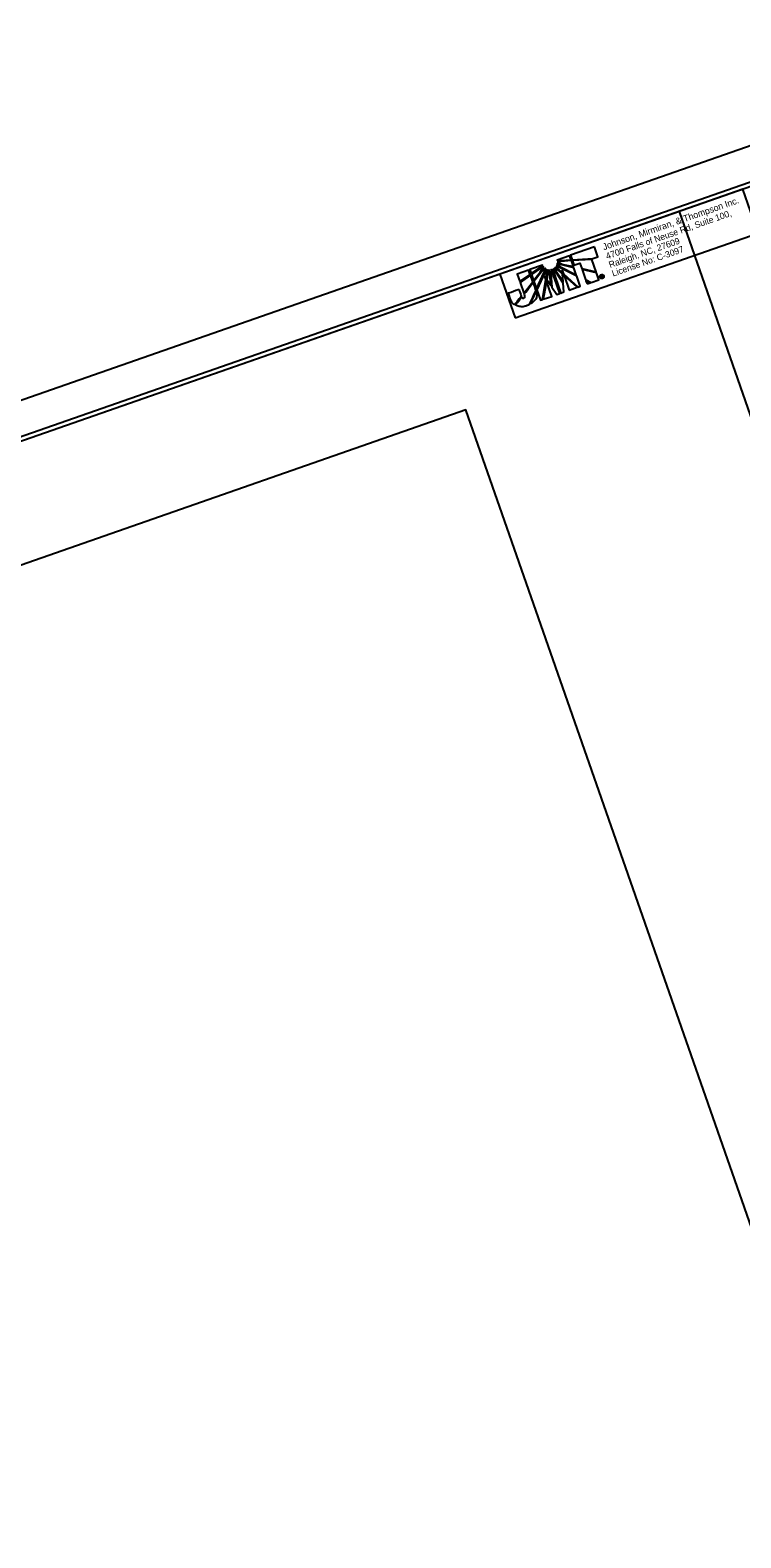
# Model space of a CAD drawing. Extents: x 1719383 to 1723601, y 969280 to 972080.
# Drawn here: x 1720360 to 1720774, y 969989 to 970869 of the extents above; entities that cross this region are included whole.
import ezdxf

# ---------------------------------------------------------------- set-up
doc = ezdxf.new("R2010")
doc.units = 0
for name, color, linetype in [('Prop Dimension Text', 7, 'Continuous'), ('Sheet Clip Boundary CELL', 7, 'Continuous'), ('Sheet Plan CELL', 7, 'Continuous'), ('Sheet Plot Border Inside CELL', 7, 'Continuous'), ('Sheet Plot Border Outside CELL', 7, 'Continuous')]:
    doc.layers.add(name, color=color, linetype=linetype)

msp = doc.modelspace()

# ---------------------------------------------------------------- linework, layer by layer
at = {"layer": 'Prop Dimension Text'}
for p, q in [((1720688.72, 970742.17), (1720674.79, 970737.29)), ((1720690.72, 970736.46), (1720688.72, 970742.17)), ((1720658.49, 970731.58), (1720651.03, 970728.97)), ((1720656.88, 970730.07), (1720658.49, 970731.58)), ((1720659.13, 970730.58), (1720657.06, 970729.56)), ((1720657.17, 970727.39), (1720659.13, 970730.58)), ((1720666.22, 970731.01), (1720667.78, 970729.18)), ((1720668.46, 970730.27), (1720666.22, 970731.01)), ((1720666.72, 970732.08), (1720668.64, 970730.71)), ((1720669.73, 970731.7), (1720666.72, 970732.08)), ((1720674.29, 970737.08), (1720666.93, 970734.54)), ((1720666.93, 970734.54), (1720669.09, 970734.31)), ((1720669.08, 970733.77), (1720666.94, 970733.31)), ((1720666.94, 970733.31), (1720670.51, 970732.01)), ((1720678.42, 970725.15), (1720668.46, 970730.27)), ((1720668.64, 970730.71), (1720678.18, 970725.83)), ((1720675.3, 970734.19), (1720669.08, 970733.77)), ((1720669.09, 970734.31), (1720675.12, 970734.7)), ((1720676.69, 970730.08), (1720669.73, 970731.7)), ((1720670.51, 970732.01), (1720676.48, 970730.67)), ((1720675.12, 970734.7), (1720674.29, 970737.08)), ((1720674.79, 970737.29), (1720675.69, 970734.73)), ((1720676.48, 970730.67), (1720675.3, 970734.19)), ((1720675.69, 970734.73), (1720675.71, 970734.66)), ((1720675.71, 970734.66), (1720687.76, 970735.43)), ((1720687.15, 970734.93), (1720675.85, 970734.26)), ((1720675.85, 970734.26), (1720675.87, 970734.22)), ((1720675.87, 970734.22), (1720676.8, 970731.55)), ((1720676.8, 970731.55), (1720680.2, 970732.74)), ((1720680.2, 970732.74), (1720681.32, 970729.56)), ((1720689.71, 970727.61), (1720687.15, 970734.93)), ((1720687.76, 970735.43), (1720690.72, 970736.46)), ((1720650.35, 970728.69), (1720643.73, 970726.37)), ((1720643.73, 970726.37), (1720645.27, 970721.98)), ((1720645.27, 970721.98), (1720651.25, 970726.14)), ((1720651.42, 970725.66), (1720645.44, 970721.48)), ((1720645.44, 970721.48), (1720647.61, 970715.3)), ((1720647.61, 970715.3), (1720652.76, 970721.82)), ((1720651.25, 970726.14), (1720650.35, 970728.69)), ((1720651.03, 970728.97), (1720651.86, 970726.6)), ((1720652.76, 970721.82), (1720651.42, 970725.66)), ((1720651.86, 970726.6), (1720656.88, 970730.07)), ((1720657.06, 970729.56), (1720652.04, 970726.08)), ((1720652.04, 970726.08), (1720653.3, 970722.5)), ((1720653.3, 970722.5), (1720657.17, 970727.39)), ((1720657.96, 970727.58), (1720653.5, 970721.92)), ((1720653.5, 970721.92), (1720654.95, 970717.78)), ((1720654.95, 970717.78), (1720659.39, 970727.5)), ((1720659.8, 970727.24), (1720655.19, 970717.08)), ((1720660.04, 970729.74), (1720657.96, 970727.58)), ((1720658.39, 970711.45), (1720660.38, 970723.13)), ((1720660.71, 970722.18), (1720658.91, 970711.63)), ((1720659.39, 970727.5), (1720660.04, 970729.74)), ((1720660.38, 970723.13), (1720659.77, 970724.88)), ((1720659.77, 970724.88), (1720660.51, 970723.8)), ((1720661.08, 970729.21), (1720659.8, 970727.24)), ((1720660.51, 970723.8), (1720661.02, 970726.81)), ((1720663.85, 970713.36), (1720660.71, 970722.18)), ((1720661.52, 970726.81), (1720660.92, 970723.24)), ((1720660.92, 970723.24), (1720663.37, 970719.63)), ((1720661.02, 970726.81), (1720661.08, 970729.21)), ((1720662.24, 970728.96), (1720661.52, 970726.81)), ((1720662.77, 970726.85), (1720662.24, 970728.96)), ((1720663.37, 970719.63), (1720662.77, 970726.85)), ((1720663.44, 970729.04), (1720663.28, 970726.6)), ((1720663.28, 970726.6), (1720663.91, 970718.79)), ((1720665.55, 970723.92), (1720663.44, 970729.04)), ((1720664.53, 970729.43), (1720666.02, 970724.08)), ((1720666.15, 970727.61), (1720664.53, 970729.43)), ((1720665.49, 970730.09), (1720666.45, 970728.05)), ((1720667.36, 970728.86), (1720665.49, 970730.09)), ((1720668.65, 970715.08), (1720665.55, 970723.92)), ((1720666.02, 970724.08), (1720669.12, 970715.25)), ((1720670.6, 970721.01), (1720666.15, 970727.61)), ((1720666.45, 970728.05), (1720670.51, 970721.96)), ((1720670.16, 970726.35), (1720667.36, 970728.86)), ((1720667.78, 970729.18), (1720670.12, 970727.04)), ((1720670.12, 970727.04), (1720670, 970728.47)), ((1720670, 970728.47), (1720670.68, 970726.53)), ((1720670.51, 970721.96), (1720670.16, 970726.35)), ((1720670.68, 970726.53), (1720679.33, 970718.79)), ((1720678.77, 970718.63), (1720671.01, 970725.58)), ((1720671.01, 970725.58), (1720674.03, 970716.97)), ((1720678.18, 970725.83), (1720676.69, 970730.08)), ((1720680.5, 970719.2), (1720678.42, 970725.15)), ((1720681.32, 970729.56), (1720689.71, 970727.61)), ((1720681.51, 970729.01), (1720683.58, 970723.09)), ((1720689.89, 970727.1), (1720681.51, 970729.01)), ((1720683.58, 970723.09), (1720686.83, 970721.41)), ((1720686.18, 970721.18), (1720683.81, 970722.44)), ((1720683.81, 970722.44), (1720684.46, 970720.58)), ((1720686.83, 970721.41), (1720691.33, 970722.99)), ((1720691.33, 970722.99), (1720689.89, 970727.1)), ((1720692.5, 970725.24), (1720692.91, 970725.38)), ((1720692.85, 970724.23), (1720692.5, 970725.24)), ((1720692.7, 970725.98), (1720692.78, 970725.77)), ((1720692.78, 970725.77), (1720692.7, 970725.98)), ((1720692.98, 970725.19), (1720692.8, 970725.13)), ((1720692.8, 970725.13), (1720692.88, 970724.89)), ((1720693.08, 970724.31), (1720692.85, 970724.23)), ((1720692.88, 970724.89), (1720693.06, 970724.95)), ((1720692.91, 970725.38), (1720692.98, 970725.41)), ((1720692.91, 970725.38), (1720692.98, 970725.19)), ((1720692.98, 970725.19), (1720692.91, 970725.38)), ((1720693.13, 970724.77), (1720692.94, 970724.7)), ((1720692.94, 970724.7), (1720693.08, 970724.31)), ((1720693.01, 970725.2), (1720692.98, 970725.19)), ((1720693.06, 970724.95), (1720693.13, 970724.77)), ((1720693.13, 970724.77), (1720693.06, 970724.95)), ((1720693.06, 970724.95), (1720693.07, 970724.95)), ((1720693.14, 970724.77), (1720693.13, 970724.77)), ((1720693.41, 970723.97), (1720693.42, 970723.98)), ((1720693.41, 970723.97), (1720693.48, 970723.75)), ((1720693.48, 970723.75), (1720693.41, 970723.97)), ((1720693.49, 970723.76), (1720693.48, 970723.75)), ((1720655.19, 970717.08), (1720657.3, 970711.07)), ((1720658.91, 970711.63), (1720663.85, 970713.36)), ((1720663.91, 970718.79), (1720666.83, 970714.45)), ((1720666.83, 970714.45), (1720668.65, 970715.08)), ((1720669.12, 970715.25), (1720670.96, 970715.89)), ((1720670.96, 970715.89), (1720670.6, 970721.01)), ((1720674.03, 970716.97), (1720678.77, 970718.63)), ((1720679.33, 970718.79), (1720680.5, 970719.2)), ((1720684.46, 970720.58), (1720686.18, 970721.18)), ((1720657.3, 970711.07), (1720658.39, 970711.45))]:
    msp.add_line(p, q, dxfattribs=at)
msp.add_lwpolyline([(1720642.59, 970700.82), (1720784.23, 970750.28), (1720775.31, 970775.84), (1720633.67, 970726.38)], close=True, dxfattribs=at)
for points in [[(1720688.72, 970742.17), (1720674.79, 970737.29), (1720675.69, 970734.73), (1720675.71, 970734.66), (1720687.76, 970735.43), (1720690.72, 970736.46), (1720688.72, 970742.17)], [(1720656.88, 970730.07), (1720658.49, 970731.58), (1720651.03, 970728.97), (1720651.86, 970726.6), (1720656.88, 970730.07)], [(1720652.04, 970726.08), (1720653.3, 970722.5), (1720657.17, 970727.39), (1720659.13, 970730.58), (1720657.06, 970729.56), (1720652.04, 970726.08)], [(1720666.22, 970731.01), (1720667.78, 970729.18), (1720670.12, 970727.04), (1720670, 970728.47), (1720670.68, 970726.53), (1720679.33, 970718.79), (1720680.5, 970719.2), (1720678.42, 970725.15), (1720668.46, 970730.27), (1720666.22, 970731.01)], [(1720666.72, 970732.08), (1720668.64, 970730.71), (1720678.18, 970725.83), (1720676.69, 970730.08), (1720669.73, 970731.7), (1720666.72, 970732.08)], [(1720669.09, 970734.31), (1720675.12, 970734.7), (1720674.29, 970737.08), (1720666.93, 970734.54), (1720669.09, 970734.31)], [(1720666.94, 970733.31), (1720670.51, 970732.01), (1720676.48, 970730.67), (1720675.3, 970734.19), (1720669.08, 970733.77), (1720666.94, 970733.31)], [(1720675.85, 970734.26), (1720675.87, 970734.22), (1720676.8, 970731.55), (1720680.2, 970732.74), (1720681.32, 970729.56), (1720689.71, 970727.61), (1720687.15, 970734.93), (1720675.85, 970734.26)], [(1720645.27, 970721.98), (1720651.25, 970726.14), (1720650.35, 970728.69), (1720643.73, 970726.37), (1720645.27, 970721.98)], [(1720647.61, 970715.3), (1720652.76, 970721.82), (1720651.42, 970725.66), (1720645.44, 970721.48), (1720647.61, 970715.3)], [(1720653.5, 970721.92), (1720654.95, 970717.78), (1720659.39, 970727.5), (1720660.04, 970729.74), (1720657.96, 970727.58), (1720653.5, 970721.92)], [(1720661.08, 970729.21), (1720659.8, 970727.24), (1720655.19, 970717.08), (1720657.3, 970711.07), (1720658.39, 970711.45), (1720660.38, 970723.13), (1720659.77, 970724.88), (1720660.51, 970723.8), (1720661.02, 970726.81), (1720661.08, 970729.21)], [(1720658.91, 970711.63), (1720663.85, 970713.36), (1720660.71, 970722.18), (1720658.91, 970711.63)], [(1720662.24, 970728.96), (1720661.52, 970726.81), (1720660.92, 970723.24), (1720663.37, 970719.63), (1720662.77, 970726.85), (1720662.24, 970728.96)], [(1720663.28, 970726.6), (1720663.91, 970718.79), (1720666.83, 970714.45), (1720668.65, 970715.08), (1720665.55, 970723.92), (1720663.44, 970729.04), (1720663.28, 970726.6)], [(1720664.53, 970729.43), (1720666.02, 970724.08), (1720669.12, 970715.25), (1720670.96, 970715.89), (1720670.6, 970721.01), (1720666.15, 970727.61), (1720664.53, 970729.43)], [(1720665.49, 970730.09), (1720666.45, 970728.05), (1720670.51, 970721.96), (1720670.16, 970726.35), (1720667.36, 970728.86), (1720665.49, 970730.09)], [(1720674.03, 970716.97), (1720678.77, 970718.63), (1720671.01, 970725.58), (1720674.03, 970716.97)], [(1720681.51, 970729.01), (1720683.58, 970723.09), (1720686.83, 970721.41), (1720691.33, 970722.99), (1720689.89, 970727.1), (1720681.51, 970729.01), (1720681.51, 970729.01)], [(1720684.46, 970720.58), (1720684.46, 970720.58), (1720686.18, 970721.18), (1720683.81, 970722.44), (1720684.46, 970720.58)], [(1720693.63, 970724.76), (1720693.65, 970724.71), (1720693.67, 970724.68), (1720693.68, 970724.64), (1720693.75, 970724.54), (1720693.53, 970724.46)]]:
    msp.add_lwpolyline(points, dxfattribs=at)
for points, degree in [([(1720693.48, 970723.75), (1720693.18, 970723.65), (1720692.87, 970723.66), (1720692.58, 970723.81), (1720692.28, 970723.94), (1720692.08, 970724.17), (1720691.97, 970724.48), (1720691.86, 970724.8), (1720691.87, 970725.1), (1720692.02, 970725.38), (1720692.17, 970725.67), (1720692.39, 970725.87), (1720692.7, 970725.98)], 3), ([(1720692.78, 970725.77), (1720692.53, 970725.68), (1720692.35, 970725.53), (1720692.23, 970725.3), (1720692.12, 970725.06), (1720692.1, 970724.81), (1720692.19, 970724.56), (1720692.27, 970724.31), (1720692.44, 970724.12), (1720692.68, 970724.01), (1720692.92, 970723.9), (1720693.16, 970723.89), (1720693.41, 970723.97)], 3), ([(1720692.7, 970725.98), (1720693.02, 970726.09), (1720693.32, 970726.07), (1720693.62, 970725.94), (1720693.91, 970725.82), (1720694.11, 970725.59), (1720694.22, 970725.27)], 3), ([(1720693.42, 970723.98), (1720693.66, 970724.06), (1720693.85, 970724.22), (1720693.96, 970724.46), (1720694.07, 970724.69), (1720694.09, 970724.95), (1720694, 970725.2), (1720693.91, 970725.45), (1720693.75, 970725.63), (1720693.51, 970725.75), (1720693.28, 970725.85), (1720693.04, 970725.86), (1720692.78, 970725.77)], 3), ([(1720692.98, 970725.41), (1720693.24, 970725.5), (1720693.4, 970725.44), (1720693.47, 970725.24), (1720693.5, 970725.15), (1720693.49, 970725.06), (1720693.43, 970724.97)], 3), ([(1720693.07, 970724.95), (1720693.22, 970725.01), (1720693.28, 970725.08), (1720693.25, 970725.16), (1720693.22, 970725.23), (1720693.15, 970725.25), (1720693.01, 970725.2)], 3), ([(1720693.33, 970724.79), (1720693.29, 970724.8), (1720693.23, 970724.8), (1720693.14, 970724.77)], 2), ([(1720693.53, 970724.46), (1720693.49, 970724.51), (1720693.45, 970724.56), (1720693.42, 970724.63), (1720693.39, 970724.72), (1720693.36, 970724.78), (1720693.33, 970724.79)], 3), ([(1720693.43, 970724.97), (1720693.51, 970724.96), (1720693.57, 970724.89), (1720693.63, 970724.76)], 2), ([(1720694.22, 970725.27), (1720694.33, 970724.96), (1720694.32, 970724.65), (1720694.18, 970724.36), (1720694.03, 970724.07), (1720693.81, 970723.87), (1720693.49, 970723.76)], 3), ([(1720644.71, 970717.47), (1720644.71, 970717.47), (1720638.57, 970715.33), (1720638.57, 970715.33), (1720638.57, 970715.33), (1720639.92, 970711.49), (1720639.92, 970711.49), (1720639.92, 970711.49), (1720640.06, 970711.08), (1720640.06, 970711.08), (1720640.48, 970709.88), (1720641.21, 970709.07), (1720642.19, 970708.51), (1720642.19, 970708.51), (1720646.16, 970713.34), (1720646.13, 970713.42), (1720646.13, 970713.42), (1720644.71, 970717.47), (1720644.71, 970717.47)], 3), ([(1720647.59, 970712.29), (1720647.2, 970712.15), (1720646.78, 970712.25), (1720646.39, 970712.93), (1720646.39, 970712.93), (1720642.66, 970708.32), (1720642.66, 970708.32), (1720644.66, 970707.29), (1720647.33, 970707.2), (1720649.31, 970707.89), (1720649.82, 970708.07), (1720650.2, 970708.25), (1720650.71, 970708.55), (1720650.71, 970708.55), (1720654.52, 970716.81), (1720654.52, 970716.81), (1720654.52, 970716.81), (1720652.95, 970721.27), (1720652.95, 970721.27), (1720652.95, 970721.27), (1720647.8, 970714.74), (1720647.8, 970714.74), (1720648.39, 970713.07), (1720648.14, 970712.48), (1720647.59, 970712.29)], 3), ([(1720647.59, 970712.29), (1720647.2, 970712.15), (1720646.78, 970712.25), (1720646.39, 970712.93), (1720646.39, 970712.93), (1720642.66, 970708.32), (1720642.66, 970708.32), (1720644.66, 970707.29), (1720647.33, 970707.2), (1720649.31, 970707.89), (1720649.82, 970708.07), (1720650.2, 970708.25), (1720650.71, 970708.55), (1720650.71, 970708.55), (1720654.52, 970716.81), (1720654.52, 970716.81), (1720654.52, 970716.81), (1720652.95, 970721.27), (1720652.95, 970721.27), (1720652.95, 970721.27), (1720647.8, 970714.74), (1720647.8, 970714.74), (1720648.39, 970713.07), (1720648.14, 970712.48), (1720647.59, 970712.29)], 3), ([(1720654.76, 970716.11), (1720654.76, 970716.11), (1720651.47, 970708.98), (1720651.47, 970708.98), (1720653.77, 970710.48), (1720655.7, 970713.04), (1720654.76, 970716.11)], 3)]:
    msp.add_open_spline(points, degree=degree, dxfattribs=at)
at = {"layer": 'Sheet Clip Boundary CELL'}
msp.add_lwpolyline([(1719941.4, 969372.44), (1721263.14, 969834), (1720986.7, 970625.64), (1720808.02, 970563.24), (1720738.29, 970762.9), (1719595.23, 970363.73)], close=True, dxfattribs=at)
at = {"layer": 'Sheet Plan CELL'}
msp.add_lwpolyline([(1720964.2, 970841.79), (1719548.03, 970347.25), (1719894.2, 969355.96), (1721310.35, 969850.49)], close=True, dxfattribs=at)
at = {"layer": 'Sheet Plot Border Inside CELL'}
msp.add_lwpolyline([(1719750.12, 969302.98), (1721322.96, 969852.25), (1720975.16, 970848.25), (1719402.3, 970299)], close=True, dxfattribs=at)
at = {"layer": 'Sheet Plot Border Outside CELL'}
for points in [[(1719744.44, 969279.81), (1721333.82, 969834.84), (1720972.81, 970868.62), (1719383.44, 970313.59)], [(1720193.92, 969542.82), (1720911.82, 969793.52), (1720613.73, 970647.14), (1719895.83, 970396.44)]]:
    msp.add_lwpolyline(points, close=True, dxfattribs=at)

# ---------------------------------------------------------------- texts
at = {"layer": 'Prop Dimension Text'}
for s, height, p in [('Johnson, Mirmiran, & Thompson Inc.', 3.8334, (1720694.28, 970740.2)), ('4700 Falls of Neuse Rd, Suite 100, ', 3.7239, (1720696.14, 970734.89)), ('Raleigh, NC, 27609', 3.7239, (1720697.89, 970729.87)), ('License No: C-3097', 3.7239, (1720699.65, 970724.85))]:
    msp.add_text(s, height=height, rotation=19.24972, dxfattribs=at).set_placement(p)

doc.saveas('drawing.dxf')
